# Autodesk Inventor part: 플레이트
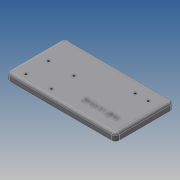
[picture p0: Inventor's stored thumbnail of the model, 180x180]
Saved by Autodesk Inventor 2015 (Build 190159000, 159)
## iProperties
Created: 2018-01
Part Number: 플레이트
Material: 알루미늄 6061
Document SubType Name: Modeling
Designer: mduedu
Density: 2.71 g/cm^3
Appearance: 기본값
Mass: 319.562 g
Surface Area: 287.617 cm^2
Volume: 117.92 cm^3
Author: mduedu
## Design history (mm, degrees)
sketch "스케치1"
  geometry: L1 (75, 40)-(-75, 40); L2 (-75, 40)-(-75, -40); L3 (-75, -40)-(75, -40); L4 (75, -40)-(75, 40); L5 (75, 40)-(-75, -40); L6 (-75, 40)-(75, -40); 1 further point
  constraints: 12 end point, 2 midpoint, 2 parallel, 1 horizontal, 1 perpendicular
  dimensions: "d0" = 150 distance of L3.end L2.end; "d1" = 80 distance of L2.end L1.end
extrude "돌출1" new body sketch "스케치1" distance "d2" = 10; taper "d3" = 0 deg
fillet "모깎기1" dims "d4" = 5
fillet "모깎기2" dims "d5" = 3
sketch "스케치2"
  geometry: L1 (-70, 40)-(70, 40) reference; L2 (-75, -35)-(-75, 35) reference; 5 further points
  constraints: 2 horizontal alignment, 2 vertical alignment
  dimensions: "d6" = 10 distance from line of point (-58, 30) L1; "d7" = 35 distance of point (-23, 30) point (-58, 30); "d8" = 31 distance of point (-58, -1) point (-58, 30); "d9" = 17 distance from line of point (-58, 30) L2
sketch "스케치3"
  geometry: 4 further points
  constraints: 4 other
hole "구멍1" sketch "스케치3" at (-23, 30), (-58, -1), (-23, -1), (-58, 30) diameter "d10" = 3.4; stored, may be unused: countersink angle "d14" = 90 deg, drill point angle "d16" = 0 deg; dims "d11" = 6, "d12" = 6.5, "d13" = 3.4, "d15" = 8
sketch "스케치4"
  geometry: L1 (75, 35)-(75, -35) reference; L2 (70, -40)-(-70, -40) reference; 3 further points
  constraints: 1 horizontal alignment
  dimensions: "d17" = 17 distance from line of point (58, -22) L1; "d18" = 18 distance of point (40, -22) point (58, -22); "d19" = 18 distance from line of point (58, -22) L2
sketch "스케치5"
  geometry: 2 further points
  constraints: 2 other
hole "구멍2" sketch "스케치5" at (40, -22), (58, -22) diameter "d20" = 3.4; stored, may be unused: countersink angle "d24" = 90 deg, drill point angle "d26" = 0 deg; dims "d21" = 6, "d22" = 6.5, "d23" = 3.4, "d25" = 8
sketch "스케치6"
  geometry: L1 (75, -35)-(75, 35) reference; L2 (-70, -40)-(70, -40) reference; 2 further points
  constraints: 1 other
  dimensions: "d27" = 40 distance from line of point (35, -20) L1; "d28" = 20 distance from line of point (35, -20) L2
feature "엠보싱1" sketch "스케치6" dims "d0" = 150, "d29" = 0.5, "d30" = 0
node "솔리드1"
